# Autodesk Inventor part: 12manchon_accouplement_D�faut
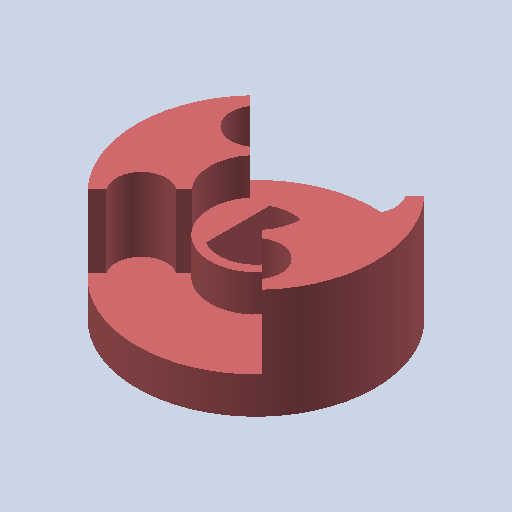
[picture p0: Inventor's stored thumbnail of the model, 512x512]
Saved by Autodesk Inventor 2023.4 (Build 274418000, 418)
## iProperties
Created: 2011-01
Part Number: 12manchon_accouplement_D�faut
Document SubType Name: Modeling
Designer: eric
Density: 1 g/cm^3
Mass: 3.50332 g
Surface Area: 22.6127 cm^2
Volume: 3.50332 cm^3
Material: Générique
Appearance: 255,128,128_1
Author: eric
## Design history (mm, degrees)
feature "Base1"
node "Corps solides"
node "Corps surfaciques"
node "Solide1"
